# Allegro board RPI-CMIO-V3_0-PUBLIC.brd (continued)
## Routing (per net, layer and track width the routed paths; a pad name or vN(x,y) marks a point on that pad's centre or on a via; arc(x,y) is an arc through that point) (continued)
CD1_SDA: length 125.7
  TOP w0.15: R17.2 5.7,93.7 5.96,93.45 5.96,92.98 5.72,92.75 J12.21
  TOP w0.2: J12.21 v1(3.55,92.75) ; J11.21 v1(3.4,39.75)
  PWRB w0.2: J6.37 64.74,47.9 20.9,47.9 12.75,39.75 v1(3.4,39.75) 3.4,40.9 5.15,42.65 5.15,62.75 4.8,63.1 4.8,90.5 3.55,91.75 v1(3.55,92.75)
CEC: length 6.9
  TOP w0.2: v1(8.06,54) J13.13 11.77,54 12.5,54.73 ; 12.5,54.73 12.73,54.5 Q3.3 ; 12.5,54.73 U4.A2
CM_1V8: length 12.2
  TOP w0.3: J1.185 v1(21.52,31.35) 20.65,31.35 C10.1 20.88,32 20.93,31.95 J1.183 v1(24.28,31.95) ; J1.186 v1(32.48,31.05) ; J1.184 v1(29.72,31.65)
  TOP w0.5: v1(37.9,20.95) R5.2 v1(39,21.85)
CM_3V3: length 11.3
  TOP w0.3: v1(24.28,29.55) J1.191 20.93,29.55 20.88,29.5 20.97,29.5 v1(21.52,28.95) J1.193 ; J1.194 v1(32.48,28.65) ; J1.192 v1(29.72,29.25)
  TOP w0.5: 20.88,29.5 C3.1 ; v1(35.1,20.95) R4.2 v1(34,21.85)
CM_VBAT: length 12
  TOP w0.3: J1.198 v1(32.48,27.45) ; C1.1 20.35,27 ; 20.35,27 21.1,27.75 v1(21.52,27.75) J1.197 ; 20.35,27 21.25,27 21.4,27.15 J1.199 v1(24.28,27.15) ; J1.200 v1(29.72,26.85)
  TOP w0.5: v1(31.5,21.85) R1.2 v1(30.4,20.95)
CM_VDAC: length 25.2
  TOP w0.3: J1.189 v1(21.52,30.15) ; J1.190 v1(32.48,29.85)
  TOP w0.5: R6.2 v1(36.5,21.85)
  PWRB w0.3: v1(32.48,29.85) 25.15,29.85 24.85,30.15 v1(21.52,30.15)
  PWRB w0.5: v1(32.48,29.85) 33.85,29.85 36.5,27.2 v1(36.5,21.85)
DAC_2V5: length 12.7
  TOP w0.3: U2.5 42.1,14.7 C5.1 v1(42.65,15)
  TOP w0.5: C5.1 41.8,15.88 41.08,16.6 37.7,16.6 36.5,17.8 R6.1
  BOTTOM w0.5: PP4.1 43.2,15 v1(42.65,15)
DSI0_CN: length 32.3
  TOP w0.116: v1(3.06,68.08) 3.35,68.37 3.8,68.37 4.2,68.37 4.33,68.25 J10.8 ; J1.105 21.73,55.35 21.55,55.18 21.35,55.18 21.15,55.38 20.95,55.38 20.75,55.18 20.55,55.18 20.35,55.38 20.15,55.38 19.95,55.18 19.75,55.18 19.63,55.3 19.27,55.3 19.15,55.18 18.12,55.18 17.3,56 17.3,60.05 17.74,60.49 v1(18.16,60.49)
  BOTTOM w0.116: v1(3.06,68.08) 3.35,68.37 8.97,68.37 17.01,60.34 17.59,60.34 17.74,60.49 v1(18.16,60.49)
DSI0_CP: length 32.3
  TOP w0.116: J1.107 21.73,54.75 21.55,54.92 18.02,54.92 17.05,55.9 17.05,60.16 17.56,60.67 v1(17.56,61.09) ; J10.9 4.33,68.75 4.2,68.63 3.7,68.63 3.35,68.63 v1(3.06,68.92)
  BOTTOM w0.116: v1(17.56,61.09) 17.56,60.67 17.48,60.59 17.11,60.59 9.07,68.63 3.35,68.63 v1(3.06,68.92)
DSI0_DN0: length 32.3
  TOP w0.116: J1.99 21.73,57.15 21.55,56.98 21.19,56.98 21.08,57.09 21.08,57.23 20.96,57.35 20.73,57.35 20.61,57.23 20.61,57.09 20.5,56.98 20.26,56.98 20.15,57.09 20.15,57.18 20.03,57.3 19.8,57.3 19.68,57.18 19.68,57.09 19.57,56.98 19.1,56.98 v1(18.8,57.27) ; J10.2 4.33,65.25 4.2,65.37 3.65,65.37 v1(3.36,65.08)
  BOTTOM w0.116: v1(3.36,65.08) 3.06,65.37 2.48,65.37 2,64.9 2,63.55 3.4,62.15 3.77,62.15 4.03,61.89 4.03,61.37 4.14,61.25 4.38,61.25 4.49,61.37 4.49,61.89 4.76,62.15 5.2,62.15 5.46,61.89 5.46,61.37 5.57,61.25 5.81,61.25 5.92,61.37 5.92,61.89 6.19,62.15 11.15,62.15 16.33,56.98 18.5,56.98 v1(18.8,57.27)
DSI0_DN1: length 32
  TOP w0.116: v1(6.72,64.08) 7.13,64.08 8.1,65.05 8.1,65.55 6.78,66.87 5.8,66.87 5.67,66.75 J10.5 ; v1(18.8,59.07) 19.1,58.78 19.95,58.78 20.15,58.98 20.35,58.98 20.55,58.78 20.75,58.78 20.95,58.98 21.15,58.98 21.35,58.78 21.55,58.78 21.73,58.95 J1.93
  BOTTOM w0.116: v1(18.8,59.07) 18.5,58.78 16.18,58.78 14.01,60.95 14.01,61.11 14.41,61.52 14.41,61.89 14.1,62.2 13.73,62.2 13.32,61.79 13.16,61.79 13,61.96 13,62.12 13.4,62.53 13.4,62.9 13.09,63.21 12.72,63.21 12.31,62.81 12.15,62.81 11.99,62.97 11.99,63.13 12.39,63.54 12.39,63.91 12.08,64.22 11.71,64.22 11.3,63.82 11.14,63.82 10.97,63.98 10.97,64.14 11.38,64.55 11.38,64.92 11.07,65.23 10.7,65.23 10.29,64.83 10.13,64.83 9.5,65.45 8.5,65.45 7.13,64.08 v1(6.72,64.08)
DSI0_DP0: length 32.3
  TOP w0.116: v1(18.8,56.43) 19.09,56.72 21.55,56.72 21.73,56.55 J1.101 ; J10.3 4.33,65.75 4.2,65.63 3.65,65.63 v1(3.36,65.92)
  BOTTOM w0.116: v1(3.36,65.92) 3.06,65.63 2.38,65.63 1.75,65 1.75,63.45 3.3,61.9 3.66,61.9 3.78,61.78 3.78,61.26 4.04,61 4.48,61 4.74,61.26 4.74,61.78 4.86,61.9 5.09,61.9 5.21,61.78 5.21,61.26 5.47,61 5.91,61 6.17,61.26 6.17,61.78 6.29,61.9 11.05,61.9 16.23,56.72 18.5,56.72 v1(18.8,56.43)
DSI0_DP1: length 32.1
  TOP w0.116: v1(18.8,58.23) 19.09,58.52 21.55,58.52 21.73,58.35 J1.95 ; J10.6 5.67,67.25 5.8,67.13 6.88,67.13 8.35,65.65 8.35,64.95 7.31,63.91 v1(7.31,63.49)
  BOTTOM w0.116: v1(18.8,58.23) 18.5,58.52 16.08,58.52 13.76,60.84 13.76,61.21 14.16,61.62 14.16,61.78 14,61.95 13.83,61.95 13.43,61.54 13.06,61.54 12.75,61.85 12.75,62.23 13.15,62.63 13.15,62.79 12.99,62.96 12.82,62.96 12.42,62.55 12.05,62.55 11.73,62.87 11.73,63.24 12.14,63.64 12.14,63.81 11.97,63.97 11.81,63.97 11.41,63.57 11.03,63.57 10.72,63.88 10.72,64.25 11.13,64.65 11.13,64.82 10.96,64.98 10.8,64.98 10.39,64.58 10.02,64.58 9.4,65.2 8.6,65.2 7.31,63.91 v1(7.31,63.49)
DSI1_CN: length 55.1
  TOP w0.115: v1(33.56,56.15) 33.28,56.44 32.44,56.44 32.25,56.25 J1.102
  TOP w0.116: J12.8 5.67,86.25 5.8,86.37 12.55,86.37 v1(12.85,86.08)
  BOTTOM w0.116: v1(33.56,56.15) 33.14,56.15 32.87,56.42 29.48,56.42 21.95,63.95 20.95,63.95 13.9,71 13.9,82.18 13.78,82.29 13.36,82.29 13.1,82.56 13.1,83 13.36,83.26 13.78,83.26 13.9,83.38 13.9,83.61 13.78,83.72 13.36,83.72 13.1,83.99 13.1,84.43 13.36,84.69 13.78,84.69 13.9,84.81 13.9,85.95 13.48,86.37 13.15,86.37 v1(12.85,86.08)
DSI1_CP: length 55.1
  TOP w0.115: J1.100 32.25,56.85 32.44,56.66 33.28,56.66 v1(33.56,56.94)
  TOP w0.116: v1(12.85,86.92) 12.55,86.63 5.8,86.63 5.67,86.75 J12.9
  BOTTOM w0.116: v1(33.56,56.94) 33.14,56.94 32.87,56.67 29.58,56.67 22.05,64.2 21.05,64.2 14.15,71.1 14.15,82.28 13.89,82.55 13.47,82.55 13.35,82.66 13.35,82.89 13.47,83.01 13.89,83.01 14.15,83.27 14.15,83.71 13.89,83.98 13.47,83.98 13.35,84.09 13.35,84.32 13.47,84.44 13.89,84.44 14.15,84.7 14.15,86.05 13.58,86.63 13.14,86.63 v1(12.85,86.92)
DSI1_DN0: length 54.9
  TOP w0.115: v1(33.56,57.96) 33.28,58.23 32.44,58.23 32.25,58.05 J1.96
  TOP w0.116: v1(15.2,83.08) 14.9,83.37 5.8,83.37 5.67,83.25 J12.2
  BOTTOM w0.116: v1(33.56,57.96) 33.14,57.96 32.87,58.22 29.53,58.22 21.95,65.8 21,65.8 16.75,70.05 16.75,77 16.63,77.12 15.86,77.12 15.6,77.38 15.6,77.82 15.86,78.09 16.63,78.09 16.75,78.2 16.75,78.43 16.63,78.55 15.86,78.55 15.6,78.81 15.6,79.25 15.86,79.52 16.63,79.52 16.75,79.63 16.75,79.86 16.63,79.98 15.86,79.98 15.6,80.24 15.6,80.68 15.86,80.95 16.63,80.95 16.75,81.06 16.75,82.55 15.93,83.37 15.5,83.37 v1(15.2,83.08)
DSI1_DN1: length 55.2
  TOP w0.115: v1(33.56,50.76) 33.28,51.03 32.44,51.03 32.25,50.85 J1.120
  TOP w0.116: J12.5 5.67,84.75 5.8,84.87 6.22,84.87 6.67,84.87 v1(6.97,84.58)
  BOTTOM w0.116: v1(6.97,84.58) 7.26,84.87 8.22,84.87 9.25,83.85 9.25,82.7 9.13,82.59 8.86,82.59 8.6,82.32 8.6,81.88 8.86,81.62 9.13,81.62 9.25,81.51 9.25,81.27 9.13,81.16 8.86,81.16 8.6,80.89 8.6,80.45 8.86,80.19 9.13,80.19 9.25,80.08 9.25,70.5 21.15,58.6 21.95,58.6 29.52,51.02 32.87,51.02 33.14,50.76 v1(33.56,50.76)
DSI1_DN2: length 55
  TOP w0.115: J1.114 32.25,52.65 32.44,52.84 33.28,52.84 v1(33.56,52.55)
  TOP w0.116: v1(6.97,87.58) 6.67,87.87 5.8,87.87 5.67,87.75 J12.11
  BOTTOM w0.116: v1(6.97,87.58) 7.26,87.87 8.73,87.87 10.45,86.15 10.45,71 21.1,60.35 22.1,60.35 29.63,52.82 32.87,52.82 33.14,52.55 v1(33.56,52.55)
DSI1_DN3: length 55
  TOP w0.115: v1(33.56,54.36) 33.28,54.63 32.44,54.63 32.25,54.45 J1.108
  TOP w0.116: v1(6.61,89.12) 6.36,89.37 5.8,89.37 5.67,89.25 J12.14
  BOTTOM w0.116: v1(6.61,89.12) 6.86,89.37 8.87,89.37 11.65,86.59 11.65,71.25 20.65,62.25 21.95,62.25 29.57,54.62 32.87,54.62 33.14,54.36 v1(33.56,54.36)
DSI1_DP0: length 54.9
  TOP w0.115: J1.94 32.25,58.65 32.44,58.47 33.28,58.47 v1(33.56,58.74)
  TOP w0.116: v1(15.2,83.92) 14.9,83.63 5.8,83.63 5.67,83.75 J12.3
  BOTTOM w0.116: v1(33.56,58.74) 33.14,58.74 32.87,58.48 29.63,58.48 22.05,66.05 21.1,66.05 17,70.15 17,77.11 16.74,77.37 15.97,77.37 15.85,77.49 15.85,77.72 15.97,77.83 16.74,77.83 17,78.1 17,78.54 16.74,78.8 15.97,78.8 15.85,78.92 15.85,79.15 15.97,79.26 16.74,79.26 17,79.53 17,79.97 16.74,80.23 15.97,80.23 15.85,80.35 15.85,80.58 15.97,80.69 16.74,80.69 17,80.96 17,82.65 16.03,83.63 15.49,83.63 v1(15.2,83.92)
DSI1_DP1: length 55.2
  TOP w0.115: v1(33.56,51.54) 33.28,51.27 32.44,51.27 32.25,51.45 J1.118
  TOP w0.116: J12.6 5.67,85.25 5.8,85.13 6.32,85.13 6.67,85.13 v1(6.97,85.42)
  BOTTOM w0.116: v1(33.56,51.54) 33.14,51.54 32.87,51.28 29.62,51.28 22.05,58.85 21.25,58.85 9.5,70.6 9.5,80.18 9.24,80.44 8.97,80.44 8.85,80.56 8.85,80.79 8.97,80.91 9.24,80.91 9.5,81.17 9.5,81.61 9.24,81.87 8.97,81.87 8.85,81.99 8.85,82.22 8.97,82.34 9.24,82.34 9.5,82.6 9.5,83.95 8.32,85.13 7.26,85.13 v1(6.97,85.42)
DSI1_DP2: length 55
  TOP w0.115: v1(33.56,53.34) 33.28,53.06 32.44,53.06 32.25,53.25 J1.112
  TOP w0.116: v1(6.97,88.42) 6.67,88.13 5.8,88.13 5.67,88.25 J12.12
  BOTTOM w0.116: v1(6.97,88.42) 7.26,88.13 8.83,88.13 10.7,86.25 10.7,71.1 21.2,60.6 22.2,60.6 29.73,53.07 32.87,53.07 33.14,53.34 v1(33.56,53.34)
DSI1_DP3: length 55
  TOP w0.115: J1.106 32.25,55.05 32.44,54.87 33.28,54.87 v1(33.56,55.14)
  TOP w0.116: J12.15 5.67,89.75 5.8,89.63 6.27,89.63 v1(6.61,89.96)
  BOTTOM w0.116: v1(33.56,55.14) 33.14,55.14 32.87,54.88 29.67,54.88 22.05,62.5 20.75,62.5 11.9,71.35 11.9,86.7 8.97,89.63 6.95,89.63 v1(6.61,89.96)
EMMC_DISABLE_N: length 137.6
  TOP w0.2: Q1.3 83.03,13 83.4,13.38 83.4,93.4 82.3,94.5 61.7,94.5 60.4,93.2 51.7,93.2 45.8,87.3 35.7,87.3 33.15,89.85 J1.2
EMMC_EN_N_1V8: length 87.5
  TOP w0.2: Q2.1 79.02,11 ; 79.02,11 79.02,13.19 72.75,19.45 72.75,44.9 69.3,48.35 63.65,48.35 52.15,59.85 J1.90 ; 79.02,11 R10.2
GPIO0: length 58.3
  TOP w0.2: J1.3 v1(24.28,89.55)
  BOTTOM w0.2: v1(24.28,89.55) 25.13,90.4 42.65,90.4 45.7,93.45 61.65,93.45 63.55,91.55 76.95,91.55 J5.1
GPIO0-27_VREF: length 43.4
  TOP w0.3: 20.8,78.75 C13.1 J1.39 v1(24.28,78.75) ; J1.40 v1(29.72,78.45)
  TOP w1: R7.1 v1(53.65,96.5)
  PWRB w1: v1(24.28,78.75) 25.18,78.75 25.48,78.45 v1(29.72,78.45) 29.72,79.52 31.95,81.75 35.35,81.75 50.1,96.5 v1(53.65,96.5)
GPIO1: length 59.1
  TOP w0.2: J1.5 v1(24.8,88.95)
  BOTTOM w0.2: J5.3 76.94,89 63.95,89 60.05,92.9 46.75,92.9 43.15,89.3 28.8,89.3 28.45,88.95 v1(24.8,88.95)
GPIO2: length 60.3
  TOP w0.2: J1.9 v1(24.28,87.75)
  BOTTOM w0.2: J5.5 76.93,86.45 61.8,86.45 55.85,92.4 48.7,92.4 45.2,88.9 29.1,88.9 27.95,87.75 v1(24.28,87.75)
GPIO3: length 57.8
  TOP w0.2: J1.11 v1(24.8,87.15)
  BOTTOM w0.2: J5.7 77.02,84 60.8,84 58.6,86.2 51.6,86.2 50.7,87.1 30.9,87.1 30.1,86.3 28.5,86.3 28,86.8 25.15,86.8 v1(24.8,87.15)
GPIO4: length 58.4
  TOP w0.2: J1.15 v1(25.2,85.95)
  BOTTOM w0.2: J5.9 76.96,81.4 62,81.4 57.85,85.55 50.95,85.55 49.75,86.75 31.65,86.75 30.85,85.95 v1(25.2,85.95)
GPIO5: length 59.3
  TOP w0.2: J1.17 v1(24.65,85.35)
  BOTTOM w0.2: v1(24.65,85.35) 25.45,85.35 25.9,84.9 31.6,84.9 32,85.3 32.5,85.3 33.4,84.4 34.2,84.4 34.7,84.9 57.1,84.9 63.15,78.85 76.95,78.85 J5.11
GPIO6: length 59.5
  TOP w0.2: J1.21 v1(25.3,84.15)
  BOTTOM w0.2: v1(25.3,84.15) 28.25,84.15 28.6,84.5 31.4,84.5 32.1,83.8 55.6,83.8 55.67,83.88 63.3,76.25 76.89,76.25 J5.13
GPIO7: length 60.5
  TOP w0.2: J1.23 v1(24.7,83.55)
  BOTTOM w0.2: J5.15 76.98,73.8 63.7,73.8 54.29,83.21 31.81,83.21 31.1,82.5 25.75,82.5 v1(24.7,83.55)
GPIO8: length 60.5
  TOP w0.2: J1.27 v1(25.05,82.35)
  BOTTOM w0.2: v1(25.05,82.35) 25.5,81.9 53.2,81.9 63.9,71.2 76.92,71.2 J5.17
GPIO9: length 61.3
  TOP w0.2: J1.29 v1(24.45,81.75)
  BOTTOM w0.2: v1(24.45,81.75) 24.8,81.4 51.2,81.4 63.9,68.7 76.96,68.7 J5.19
GPIO10: length 61.8
  TOP w0.2: J1.33 v1(25.05,80.55)
  BOTTOM w0.2: v1(25.05,80.55) 25.39,80.21 50.04,80.21 64.05,66.2 77,66.2 J5.21
GPIO11: length 62.6
  TOP w0.2: J1.35 v1(24.28,79.95)
  BOTTOM w0.2: J5.23 76.99,63.65 64.1,63.65 48.14,79.61 24.61,79.61 v1(24.28,79.95)
GPIO12: length 60.9
  TOP w0.2: J1.45 v1(24.95,73.35)
  BOTTOM w0.2: J5.25 76.98,61.1 63.85,61.1 52.05,72.9 25.4,72.9 v1(24.95,73.35)
GPIO13: length 61.7
  TOP w0.2: J1.47 v1(24.45,72.75)
  BOTTOM w0.2: J5.27 77.02,58.6 63.25,58.6 49.5,72.35 24.85,72.35 v1(24.45,72.75)
GPIO14: length 62.3
  TOP w0.2: J1.51 v1(25.05,71.55)
  BOTTOM w0.2: v1(25.05,71.55) 25.4,71.2 48.55,71.2 63.75,56 76.96,56 J5.29
GPIO15: length 63.1
  TOP w0.2: J1.53 v1(24.45,70.95)
  BOTTOM w0.2: J5.31 77,53.5 63.7,53.5 46.6,70.6 24.8,70.6 v1(24.45,70.95)
GPIO16: length 63.6
  TOP w0.2: J1.57 v1(25,69.75)
  BOTTOM w0.2: v1(25,69.75) 25.34,69.41 43.85,69.41 45.29,69.41 63.75,50.95 76.99,50.95 J5.33
GPIO17: length 64.4
  TOP w0.2: J1.59 v1(24.28,69.15)
  BOTTOM w0.2: v1(24.28,69.15) 24.61,68.81 43.29,68.81 63.7,48.4 76.98,48.4 J5.35
GPIO18: length 65
  TOP w0.2: J1.63 v1(25.05,67.95)
  BOTTOM w0.2: J5.37 76.92,45.8 63.45,45.8 41.64,67.61 25.39,67.61 v1(25.05,67.95)
GPIO19: length 65.8
  TOP w0.2: J1.65 v1(24.28,67.35)
  BOTTOM w0.2: J5.39 76.96,43.3 63.5,43.3 39.79,67.01 24.61,67.01 v1(24.28,67.35)
GPIO20: length 66.4
  TOP w0.2: J1.69 v1(24.85,66.15)
  BOTTOM w0.2: J5.41 76.95,40.75 63.4,40.75 38.34,65.81 25.19,65.81 v1(24.85,66.15)
GPIO21: length 67.2
  TOP w0.2: J1.71 v1(24.28,65.55)
  BOTTOM w0.2: v1(24.28,65.55) 24.61,65.21 36.29,65.21 63.25,38.25 76.99,38.25 J5.43
GPIO22: length 67.7
  TOP w0.2: J1.75 v1(26.25,64.35)
  BOTTOM w0.2: J5.45 77.03,35.75 63.85,35.75 35.59,64.01 26.59,64.01 v1(26.25,64.35)
GPIO23: length 69.5
  TOP w0.2: J1.77 v1(25.5,63.75)
  BOTTOM w0.2: J5.47 76.92,33.1 63.85,33.1 62.42,34.53 62.42,36.08 35.09,63.41 25.84,63.41 v1(25.5,63.75)
GPIO24: length 70.8
  TOP w0.2: J1.81 v1(28.9,62.55)
  BOTTOM w0.2: v1(28.9,62.55) 29.24,62.21 34.99,62.21 61.18,36.02 61.18,33.17 63.85,30.5 76.86,30.5 J5.49
GPIO25: length 72.4
  TOP w0.2: J1.83 v1(28.15,61.95)
  BOTTOM w0.2: v1(28.15,61.95) 28.49,61.61 34.49,61.61 60.14,35.96 60.14,31.76 63.95,27.95 76.85,27.95 J5.51
GPIO26: length 73.8
  TOP w0.2: J1.87 v1(28.35,60.75)
  BOTTOM w0.2: J5.53 76.89,25.45 63.85,25.45 58.8,30.5 58.8,36.15 34.55,60.4 30.3,60.4 29.95,60.75 v1(28.35,60.75)
GPIO27: length 75.2
  TOP w0.2: J1.89 v1(29.3,60.15)
  BOTTOM w0.2: v1(29.3,60.15) 29.64,59.81 33.94,59.81 57.95,35.8 57.95,29 63.95,23 76.98,23 J5.55
GPIO28: length 39.5
  TOP w0.2: J1.28 34.15,82.05 ; 34.15,82.05 54.75,82.05 J6.1 ; 34.15,82.05 34.19,82.08 R27.1
GPIO28-45_VREF: length 43.6
  TOP w0.3: 20.8,74.55 C14.1 J1.41 v1(24.28,74.55) ; J1.42 v1(29.72,74.25)
  TOP w1: R8.1 v1(53.65,94.5)
  PWRB w1: v1(24.28,74.55) 29.42,74.55 v1(29.72,74.25) 49.97,94.5 v1(53.65,94.5)
GPIO29: length 38.7
  TOP w0.2: R26.1 34.19,81.42 34.15,81.45 ; J1.30 34.15,81.45 ; 34.15,81.45 56.69,81.45 J6.3
GPIO30: length 37.5
  TOP w0.2: J1.34 58.03,80.25 J6.5
GPIO31: length 36.7
  TOP w0.2: J6.7 59.97,79.65 J1.36
GPIO32: length 38.4
  TOP w0.2: J6.9 55.91,73.05 J1.46
GPIO33: length 37.6
  TOP w0.2: J1.48 57.85,72.45 J6.11
GPIO34: length 37.1
  TOP w0.2: J1.52 59.19,71.25 J6.13
GPIO35: length 36.3
  TOP w0.2: J1.54 61.13,70.65 J6.15
GPIO36: length 35.7
  TOP w0.2: J6.17 62.47,69.45 J1.58
GPIO37: length 34.9
  TOP w0.2: J1.60 64.41,68.85 J6.19
GPIO38: length 34.5
  TOP w0.2: J6.21 64.5,67.43 64.28,67.65 J1.64
GPIO39: length 35.3
  TOP w0.2: J1.66 63.37,67.05 J6.23
GPIO40: length 35.9
  TOP w0.2: J1.70 62.03,65.85 J6.25
GPIO41: length 36.7
  TOP w0.2: J1.72 60.09,65.25 J6.27
GPIO42: length 37.2
  TOP w0.2: J6.29 58.75,64.05 J1.76
GPIO43: length 38
  TOP w0.2: J1.78 56.81,63.45 J6.31
GPIO44: length 39.2
  TOP w0.2: R29.1 34.19,62.27 34.2,62.25 ; 34.2,62.25 J1.82 ; 34.2,62.25 55.47,62.25 J6.33
GPIO45: length 40
  TOP w0.2: 37.45,61.65 53.53,61.65 J6.35 ; 37.45,61.65 J1.84 ; 37.45,61.65 37.47,61.63 R28.1
H5V: length 20.9
  TOP w0.2: J13.18 7.3,56.5 v1(7.1,56.3) ; U4.C1 v1(13.42,55.9) ; Q3.1 v1(15.02,54) ; U4.A1 v1(13.42,55.1)
  TOP w0.3: v1(13.42,55.9) 13.79,56.27 13.79,56.51 14.75,57.48 U3.2 14.75,57.92 15.34,58.52 C16.1
  PWRT w0.3: v1(7.1,56.3) 7.85,57.05 13.02,57.05 13.42,56.65 v1(13.42,55.9) v1(13.42,55.1) 13.42,54.43 13.85,54 v1(15.02,54)
  BOTTOM w0.5: v1(15.02,54) 15.02,52.52 PP10.1
HDMI_CEC: length 26.4
  TOP w0.2: v1(16.75,55) Q3.2 14.9,55 14.52,55.38 R15.1 ; J1.171 v1(20.6,35.55)
  PWRT w0.2: v1(20.6,35.55) 20.6,47.55 16.75,51.4 v1(16.75,55)
HDMI_CK_N: length 13.5
  TOP w0.116: J1.111 21.73,53.55 21.55,53.38 19.97,53.38 19.72,53.13 11.94,53.13 11.56,53.5 J13.12
HDMI_CK_P: length 13.5
  TOP w0.116: J13.10 11.56,52.5 11.94,52.87 19.82,52.87 20.07,53.12 21.55,53.12 21.73,52.95 J1.113
HDMI_D0_N: length 13.3
  TOP w0.116: J1.117 21.73,51.75 21.71,51.74 11.83,51.74 11.56,52 J13.9
HDMI_D0_P: length 13.5
  TOP w0.116: J1.119 21.73,51.15 21.39,51.48 12.05,51.48 11.56,51 J13.7
HDMI_D1_N: length 13.5
  TOP w0.116: J13.6 11.56,50.5 11.94,50.13 19.82,50.13 20.17,49.78 21.55,49.78 21.73,49.95 J1.123
HDMI_D1_P: length 13.5
  TOP w0.116: J1.125 21.73,49.35 21.55,49.52 20.07,49.52 19.72,49.87 11.94,49.87 11.56,49.5 J13.4
HDMI_D2_N: length 13.7
  TOP w0.116: J1.129 21.73,48.15 21.55,47.98 19.82,47.98 19.17,48.63 11.94,48.63 11.56,49 J13.3
HDMI_D2_P: length 13.7
  TOP w0.116: J13.1 11.56,48 11.94,48.37 19.07,48.37 19.72,47.72 21.55,47.72 21.73,47.55 J1.131
HDMI_HPD: length 13.4
  TOP w0.2: U4.C3 12.1,56.03 11.95,56.18 11.95,56.42 11.37,57 J13.19 7.2,57 5.9,58.3 5.9,61.6 6.8,62.5 Q4.1
HDMI_HPD_N_1V8: length 31.3
  TOP w0.2: Q4.3 9.8,61.65 9.93,61.52 11,61.52 R18.2 v1(11,60.85) ; J1.88 33.45,60.45 v1(34,61)
  PWRB w0.2: v1(11,60.85) 12.55,62.4 24.9,62.4 28.35,58.95 29.85,58.95 31,60.1 33.1,60.1 v1(34,61)
HDMI_SCL: length 35.2
  TOP w0.2: J1.175 v1(20.6,34.35) ; v1(7.55,54.8) 8.01,54.8 8.21,55 J13.15 11.27,55 11.37,55.1 U4.A3
  PWRT w0.2: v1(7.55,54.8) 10.8,54.8 19,46.6 19,35.2 19.85,34.35 v1(20.6,34.35)
HDMI_SDA: length 35.2
  TOP w0.2: J1.173 v1(21.2,34.95) ; U4.B3 J13.16 v1(7.55,55.5)
  PWRT w0.2: v1(7.55,55.5) 11.2,55.5 19.75,46.95 19.75,35.35 20.15,34.95 v1(21.2,34.95)
RUN: length 148.7
  TOP w0.2: J1.177 v1(24.28,33.75) ; J7.1 32.55,99.15 32.9,98.8 v1(32.9,98.3)
  PWRT w0.2: v1(24.28,33.75) 33.65,33.75 35.4,32 37.4,32 39,33.6 39,92.2 v1(32.9,98.3)
  BOTTOM w0.2: v1(24.28,33.75) 25.33,34.8 36.8,34.8 37.8,33.8 52.8,33.8 57.15,29.45 57.15,27.2 63.9,20.45 76.97,20.45 J5.57
SDX_CLK: length 24.4
  TOP w0.15: v1(29.3,87.45) J1.10
  TOP w0.2: J16.5 15.8,102.94 v1(15.8,102)
  PWRT w0.15: v1(15.8,102) 15.8,100.95 v1(29.3,87.45)
  BOTTOM w0.2: v1(15.8,102) PP15.1
SDX_CMD: length 26.2
  TOP w0.15: v1(29,86.85) J1.12
  TOP w0.2: J16.3 13.6,102.94 v1(13.6,102)
  PWRT w0.15: v1(29,86.85) 14.6,101.25 14.35,101.25 v1(13.6,102)
  BOTTOM w0.2: v1(13.6,102) 13.55,101.25 13.5,100.99 PP14.1
SDX_D0: length 27.9
  TOP w0.15: J1.16 v1(33,85.65)
  TOP w0.2: v1(18,102) 18,102.94 J16.7
  PWRT w0.15: v1(33,85.65) 33,86.8 28.4,91.4 28.4,92.7 22.95,98.15 22.43,98.15 21.89,98.7 21.3,98.7 v1(18,102)
  BOTTOM w0.2: v1(18,102) PP16.1
SDX_D1: length 29.7
  TOP w0.15: J1.18 v1(33.6,85.05)
  TOP w0.2: J16.8 19.05,102.94 v1(19.05,102)
  PWRT w0.15: v1(33.6,85.05) 33.6,88.05 29.2,92.45 29.2,93.3 20.5,102 v1(19.05,102)
  BOTTOM w0.2: v1(19.05,102) PP17.1
SDX_D2: length 30.6
  TOP w0.15: J1.22 v1(29.2,83.85)
  TOP w0.2: v1(11.4,102) 11.4,102.94 J16.1
  PWRT w0.15: v1(29.2,83.85) 29.2,85.4 23,91.6 22.39,91.6 13.79,100.2 13.2,100.2 v1(11.4,102)
  BOTTOM w0.2: v1(11.4,102) PP12.1
SDX_D3: length 30.2
  TOP w0.15: J1.24 v1(29.7,83.25)
  TOP w0.2: J16.2 12.5,102.94 v1(12.5,102)
  PWRT w0.15: v1(12.5,102) 13.7,100.8 14.29,100.8 29.7,85.39 v1(29.7,83.25)
  BOTTOM w0.2: v1(12.5,102) PP13.1
SDX_VREF: length 16.3
  TOP w0.3: J1.6 29.35,88.65 29,89 29.25,89.25 J1.4
  TOP w0.5: R31.1 24.35,96.1 24.35,97.95 C23.1
  TOP w1: 29,89 29,93 26,96 R31.1
TVDAC: length 41.8
  TOP w0.125: J6.59 57.73,19.17 39.85,37.05 J1.166
USB_DM: length 18.3
  TOP w0.136: U5.2 25.3,21.95 25.37,22.02 25.37,35.32 25.24,35.46 25.14,35.46 25,35.6 25,35.87 25.14,36 25.24,36 25.37,36.14 25.37,36.43 24.88,36.92 24.25,36.92 24.08,36.75 J1.167
USB_DP: length 18.3
  TOP w0.136: U5.1 25.7,21.95 25.63,22.02 25.63,36.53 24.98,37.18 24.25,37.18 24.08,37.35 J1.165
USB_OTGID: length 46.2
  TOP w0.2: 63.25,24.25 61.69,22.68 R12.2 ; 63.25,24.25 v1(55.4,32.1) ; 63.25,24.25 J6.55 ; v1(39.9,35.3) 38.75,36.45 J1.168
  BOTTOM w0.2: v1(55.4,32.1) 52.2,35.3 v1(39.9,35.3)
USBA_DM: length 10.4
  TOP w0.136: J14.2 28.37,12.37 28.37,15.07 25.37,18.07 25.37,19.64 25.3,19.71 U5.6
USBA_DP: length 10.4
  TOP w0.136: U5.7 25.7,19.71 25.63,19.64 25.63,18.17 28.63,15.17 28.63,12.37 J14.3
USBB_DM: length 25.1
  TOP w0.136: U5.4 24.21,20.8 24.14,20.73 17.13,20.73 13.55,17.15 13.55,6.08 13.35,5.88 J15.2
USBB_DP: length 25.1
  TOP w0.136: U5.5 24.21,20.4 24.14,20.47 23.85,20.47 23.71,20.34 23.71,20.34 23.58,20.2 23.31,20.2 23.17,20.34 23.17,20.34 23.03,20.47 22.76,20.47 22.63,20.34 22.63,20.34 22.49,20.2 22.22,20.2 22.08,20.34 22.08,20.34 21.95,20.47 17.23,20.47 13.8,17.05 13.8,6.08 14,5.88 J15.3
VC_TCK: length 74.6
  TOP w0.2: J1.180 v1(35.75,32.85) ; v1(29.05,98.3) J7.8
  PWRT w0.2: v1(35.75,32.85) 35.75,90.35 29.05,97.05 v1(29.05,98.3)
VC_TDI: length 74.8
  TOP w0.2: J1.174 v1(37.9,34.65) ; J7.3 v1(31.55,98.3)
  PWRT w0.2: v1(31.55,98.3) 31.55,97.35 37.9,91 v1(37.9,34.65)
VC_TDO: length 75.4
  TOP w0.2: J1.178 v1(37.2,33.45) ; J7.5 v1(30.55,98.3)
  PWRT w0.2: v1(37.2,33.45) 37.2,90.75 30.55,97.4 v1(30.55,98.3)
VC_TMS: length 74.1
  TOP w0.2: v1(29.8,98) 29.8,98.5 30.05,98.75 J7.6 ; J1.176 v1(36.4,34.05)
  PWRT w0.2: v1(36.4,34.05) 36.4,90.65 29.8,97.25 v1(29.8,98)
VC_TRST_N: length 74.8
  TOP w0.2: v1(32.2,98.3) 32.2,99 32.05,99.15 J7.2 ; J1.172 v1(38.5,35.25)
  PWRT w0.2: v1(38.5,35.25) 38.5,91.3 32.2,97.6 v1(32.2,98.3)
VG0: length 27.3
  TOP w1: J3.3 67,102.7 66,103.7 63.48,103.7 56.45,96.67 R7.2
  PWRB w1: 83.5,29.33 J5.52 ; J3.3 67,103.4 ; 83.5,59.5 83.5,59.81 J5.28 ; 83,75.05 J5.16 ; 83.5,44.57 J5.40
VG1: length 27.8
  TOP w1: R8.2 57.6,94.5 59.9,96.8 66.23,96.8 67,97.57 J3.4
  PWRB w1: 67,96.5 J3.4 ; J6.28 70.69,59.81 71,59.5 ; 70.93,44.57 J6.40 ; 70.83,29.33 J6.52 ; 70.95,75.05 J6.16
N1195355: length 5.3
  TOP w0.3: 47.8,5.42 R9.2 v1(47.8,3.3) D2.2
  BOTTOM w0.3: PP9.1 46.3,3.3 v1(47.8,3.3)
N1195439: length 56.2
  TOP w0.2: D2.1 46.2,11.2 50.4,15.4 73.2,15.4 77.2,11.4 77.2,9.6 78.4,8.4 82.4,8.4 82.8,8.8 Q2.3 82.8,11.12 81.42,12.5 Q1.2
N1202496: length 2.6
  TOP w0.2: U1.12 61.2,9.14 61.22,9.16 R2.2 C6.1
N1202592: length 3.1
  TOP w0.25: U1.8 63.2,6.83 L1.1
N1202604: length 3.1
  TOP w0.25: U1.2 55.8,8.18 L2.1
N1202780: length 6
  TOP w0.4: J2.1 71.7,6.7 F1.1
  TOP w0.5: F1.1 v1(71,9)
  BOTTOM w0.5: v1(71,9) PP1.1
N1203166: length 1.4
  TOP w0.3: U2.4 42.1,11.81 C9.1
N1203318: length 7.6
  TOP w0.3: D1.2 v1(52.8,3.3) 50.69,5.42 R3.2
  BOTTOM w0.3: v1(52.8,3.3) 52.8,2.8 PP7.1
N1313759: length 3.6
  TOP w0.2: R25.1 C21.2 R22.2 56.94,7.29 56.95,7.28 U1.4
N1313939: length 3.6
  TOP w0.2: U1.10 62.05,7.72 62.06,7.71 64.8,7.71
N1329395: length 32.3
  TOP w0.2: U5.10 26.85,21.2 v1(27.3,21.65) ; 9.38,8.5 R20.2 10.18,8.5 10.47,8.2 Q5.3 v1(10.9,7.42)
  BOTTOM w0.2: v1(27.3,21.65) 26.45,22.5 20,22.5 12.5,15 12.5,9.02 v1(10.9,7.42) 10.38,7.94 10.38,8.12 PP11.1
N1357591: length 70.1
  TOP w0.2: v1(80.2,13.5) Q1.1 81.2,14.29 R30.1
  BOTTOM w0.2: J4.2 21.2,17.2 48.5,17.2 50.9,14.8 78.9,14.8 v1(80.2,13.5)

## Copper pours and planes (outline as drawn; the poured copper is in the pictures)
1V8 on PWRT: 0.5,101 4,104.5 81,104.5 84.5,101 84.5,4 81,0.5 4,0.5 0.5,4 ; 7 cut-outs
3V3 on PWRB: 81,0.5 4,0.5 0.5,4 0.5,101 4,104.5 81,104.5 84.5,101 84.5,4 ; 12 cut-outs
5V on PWRT: 4,0.5 0.5,4 0.5,61 12,61 12.5,60.5 12.5,11.1 12.9,10.7 67.2,10.7 68.5,12 82,12 82,23 67,23 66.5,23.5 66.5,25 67,25.5 81.1,25.5 81.1,89 67,89 66.5,89.5 66.5,93.8 66.8,94.1 84.5,94.1 84.5,4 81,0.5 ; 1 cut-out
GND on TOP: 60.5,13.3 60.5,8.8 60.4,8.8 60.4,6.2 60.15,6.2 60.15,2.25 58.5,2.25 58.5,5.75 58.6,5.75 58.6,8.8 58.85,8.8 58.85,13.3
GND on TOP: 81,0.5 77.1,0.5 77.1,6 68.9,6 68.9,0.5 18.1,0.5 18.1,6 9.9,6 9.9,0.5 4,0.5 0.5,4 0.5,101 4,104.5 81,104.5 84.5,101 84.5,4 ; 8 cut-outs
GND on BOTTOM: 84.5,4 81,0.5 4,0.5 0.5,4 0.5,101 4,104.5 81,104.5 84.5,101 ; 39 cut-outs
GND on GNDT, GNDB: 81,0.5 4,0.5 0.5,4 0.5,101 4,104.5 81,104.5 84.5,101 84.5,4
CM_1V8 on PWRB: 21.3,32.2 21.3,30.8 33.8,30.8 37.2,27.4 37.2,20.6 40.3,20.6 40.3,28.2 36.3,32.2
CM_3V3 on PWRB: 21.3,29.8 21.3,28.4 32.7,28.4 33,28.1 33,20.6 35.7,20.6 35.7,27.1 33.4,29.4 32.3,29.4 31.8,29.5 24.9,29.5 24.6,29.8
CM_VBAT on PWRB: 21.3,28 21.3,26.6 30.1,26.6 30.1,20.6 32.7,20.6 32.7,28
VG0 on PWRB: 82.5,29 82.5,94 79.5,94 70.5,103 66.5,103 66,103.5 66,104.5 81,104.5 84.5,101 84.5,29 84,28.5 83,28.5
VG1 on PWRB: 66.5,97.5 66,97 66,96 66.5,95.5 69.5,95.5 70,95 70,29 70.5,28.5 71.5,28.5 72,29 72,97 71.5,97.5

Small or netless copper shapes (teardrops, artwork), in the pictures only: 272 on TOP, 78 on BOTTOM, 17 on PWRT, 17 on PWRB

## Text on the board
BOTTOM: L06 - BOTTOM
Ref Des/Silkscreen Bottom: BOTTOM COMPONENT LEGEND
User.Comments: TOP SOLDER MASK | BOTTOM SOLDER MASK
TOP: L01 - TOP
Package Geometry/Pastemask Top: TOP PASTE MASK
Ref Des/Silkscreen Top: GND | 5V0 | 3V3 | 1V8 | VG1 | NC | VG0 | EN | USB SLAVE | DIS | BOOT ENABLE | USB_ | CD1_SDA | CD1_SCL | CAM1_IO1 | CAM1_IO0 | CD0_SDA | CD0_SCL | CAM0_IO1 | CAM0_IO0 | 28 | 29 | 30 | 31 | 32 | 33 | 34 | 35 | 36 | 37 | 38 | 39 | 40 | 41 | 42 | 43 | 44 | 45 | VDD_CORE | TVDAC | OTGID | 0 | 1 | 2 | 3 | 4 | 5 | 6 | 7 | 8 | 9 | 10 | 11 | 12 | 13 | 14 | 15 | 16 | 17 | 18 | 19 | 20 | 21 | 22 | 23 | 24 | 25 | 26 | 27 | RUN | VG0 SELCT | VG1 SELCT | GPIOx BANK 1 | GPIOx BANK 0 | SD CARD ONLY FOR | MODULES WITHOUT | ON-BOARD FLASH | VC JTAG | ACT | Made in the UK | Compute Module IO Board V3.0 | (c) Raspberry Pi 2014/15 | PWR | USB HOST | POWER IN | DISP1 | TOP COMPONENT LEGEND | DISP0 | CAM1 | CAM0 | RASPBERRY PI COMPUTE MODULE | OR COMPUTE MODULE 3
GNDT: L02 - GND
PWRT: L03 - PWR/ROUTING
PWRB: L04 - PWR/ROUTING
GNDB: L05 - GND
DIMENSION: NONE | DRILL DWG / MECHANICAL | (ON TOP SIDE) | ADD MANUFACTURING CODES HERE | ROUTE TOP AND BOTTOM (SHORT) EDGES | V-SCORE LEFT AND RIGHT (LONG) EDGES | BOARD PANELISATION:
NCLEGEND-1-6: FIGURE | SIZE | 0.25 | 1.0 | 2.3 | 1.1 | 1.6 | 2.4 | 3.4 | 1.05x0.65 | 1.4x0.7 | 1.7x0.9 | 2.7x0.9 | DRILL CHART: TOP to BOTTOM | ALL UNITS ARE IN MILLIMETERS | PLATED | NON-PLATED | QTY | 476 | 133 | 2 | 1 | 4
